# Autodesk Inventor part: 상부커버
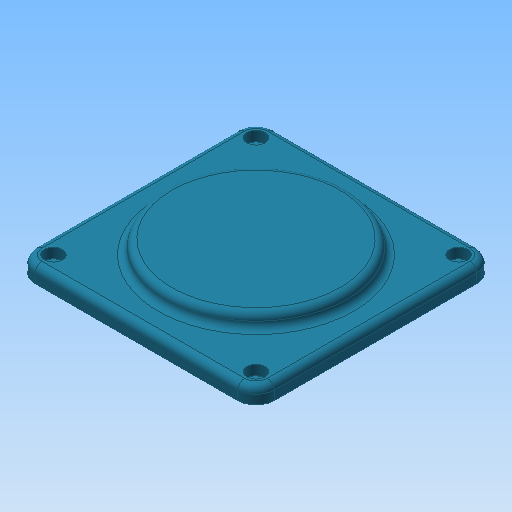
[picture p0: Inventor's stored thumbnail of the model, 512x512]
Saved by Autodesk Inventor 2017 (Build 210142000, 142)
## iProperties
Created: 2018-09
Part Number: 상부커버
Document SubType Name: Modeling
Density: 2.71 g/cm^3
Material: 알루미늄 6061
Mass: 284.928 g
Surface Area: 255.797 cm^2
Volume: 105.139 cm^3
Appearance: 터키옥색
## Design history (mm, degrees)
sketch "스케치5"
  geometry: L1 (-52.5, -52.5)-(52.5, -52.5); L2 (52.5, -52.5)-(52.5, 52.5); L3 (52.5, 52.5)-(-52.5, 52.5); L4 (-52.5, 52.5)-(-52.5, -52.5); L5 (-52.5, -52.5)-(52.5, 52.5); L6 (52.5, -52.5)-(-52.5, 52.5); 1 further point
  constraints: 12 end point, 2 midpoint, 2 parallel, 1 horizontal, 1 perpendicular
  dimensions: "d35" = 105 distance of L3.end L2.end; "d36" = 105 distance of L2.end L1.end
extrude "돌출4" new body sketch "스케치5" distance "d37" = 7; taper "d38" = 0 deg
fillet "모깎기4" dims "d39" = 8
sketch "스케치2"
  geometry: C1 r 40 at (0, 0); 2 further points
  constraints: 2 coincident, 1 centre point
  dimensions: "d4" = 80 diameter of C1
extrude "돌출3" join sketch "스케치2" distance "d5" = 6; taper "d6" = 0 deg
fillet "모깎기1" dims "d7" = 3
sketch "스케치4"
  geometry: L1 (52.5, -44.5)-(52.5, 44.5) reference; L2 (-44.5, -52.5)-(44.5, -52.5) reference; L3 (-52.5, 44.5)-(-52.5, -44.5) reference; L4 (44.5, 52.5)-(-44.5, 52.5) reference; A1 r 8 centre (44.5, 44.5) between (52.5, 44.5) and (44.5, 52.5) reference; A2 r 8 centre (44.5, -44.5) between (44.5, -52.5) and (52.5, -44.5) reference; A3 r 8 centre (-44.5, -44.5) between (-52.5, -44.5) and (-44.5, -52.5) reference; A4 r 8 centre (-44.5, 44.5) between (-44.5, 52.5) and (-52.5, 44.5) reference; 4 further points
  constraints: 4 coincident
hole "구멍3" sketch "스케치4" at (-44.5, 44.5), (-44.5, -44.5), (44.5, -44.5), (44.5, 44.5) diameter "d43" = 4.5; stored, may be unused: countersink angle "d47" = 90 deg, drill point angle "d49" = 118 deg; dims "d44" = 6, "d45" = 8, "d46" = 4.4, "d48" = 8
fillet "모깎기3" dims "d19" = 3
node "솔리드1"
node "솔리드2"
node "투영된 루프2"
